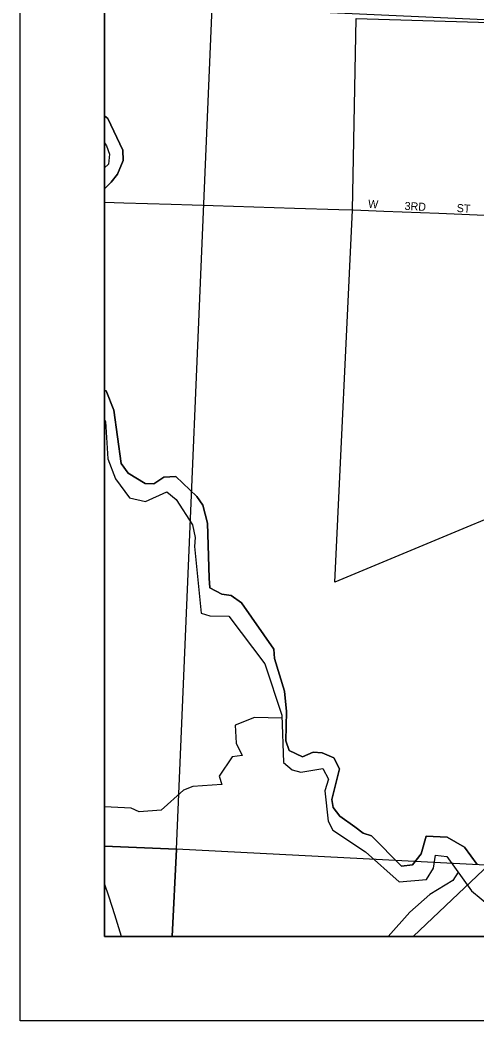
# Model space of a CAD drawing. Extents: x 0 to 34, y 0 to 22.
# Drawn here: x 23.917 to 24.458, y 14 to 15.184 of the extents above; entities that cross this region are included whole.
import ezdxf

# ---------------------------------------------------------------- set-up
doc = ezdxf.new("R2010")
doc.units = 0
for name, color, linetype in [('GM_X_Adjacent_County', 7, 'Continuous'), ('GM_X_City_Street', 7, 'Continuous'), ('GM_X_City_Street_Text', 7, 'Continuous'), ('GM_X_Corporation', 7, 'Continuous'), ('GM_X_County', 7, 'Continuous'), ('GM_X_County_Road', 7, 'Continuous'), ('GM_X_Minor_River', 7, 'Continuous'), ('GM_X_Section', 7, 'Continuous'), ('GM_X_Township', 7, 'Continuous'), ('GM_X_Township_Road', 7, 'Continuous'), ('SH_Data', 7, 'Continuous')]:
    doc.layers.add(name, color=color, linetype=linetype)

msp = doc.modelspace()

# ---------------------------------------------------------------- linework, layer by layer
at = {"layer": 'GM_X_Adjacent_County'}
msp.add_lwpolyline([(24.0167, 18.0693), (24.0167, 14.1), (30.8167, 14.1), (30.8167, 17.8174)], dxfattribs=at)
at = {"layer": 'GM_X_City_Street'}
msp.add_lwpolyline([(24.3111, 14.9597), (24.3112, 14.9597), (24.3473, 14.9583), (24.4126, 14.9558), (24.476, 14.9533)], dxfattribs=at)
at = {"layer": 'GM_X_Corporation'}
msp.add_lwpolyline([(25.6279, 15.253), (25.399, 15.0362), (25.3871, 15.0255), (25.3906, 15.0196), (25.3564, 14.389), (25.0022, 14.3996), (24.6145, 14.4222), (24.623, 14.6582), (24.2893, 14.5192), (24.3104, 14.9594), (24.3146, 15.1862), (24.6178, 15.1772), (24.7267, 15.1736), (24.7351, 15.3783)], dxfattribs=at)
at = {"layer": 'GM_X_County'}
msp.add_lwpolyline([(24.0167, 18.0693), (24.0167, 14.1), (30.8167, 14.1), (30.8167, 17.8174)], dxfattribs=at)
at = {"layer": 'GM_X_County_Road'}
for points in [[(24.0167, 14.969), (24.0397, 14.9683), (24.0956, 14.9665), (24.1453, 14.965), (24.2416, 14.9619), (24.2943, 14.9602), (24.3111, 14.9597)], [(24.3821, 14.1), (24.4359, 14.1508), (24.4651, 14.1786), (24.5086, 14.2203), (24.5687, 14.277), (24.6139, 14.3196), (24.6339, 14.3391), (24.6534, 14.3591), (24.6896, 14.3975), (24.6989, 14.4075)]]:
    msp.add_lwpolyline(points, dxfattribs=at)
at = {"layer": 'GM_X_Minor_River'}
for points in [[(24.0167, 14.9847), (24.0245, 14.9926), (24.032, 15.0021), (24.0388, 15.0181), (24.0384, 15.0306), (24.0208, 15.0681), (24.0167, 15.0709)], [(24.0167, 15.0709), (24.0208, 15.0681), (24.0384, 15.0306), (24.0388, 15.0181), (24.032, 15.0021), (24.0245, 14.9926), (24.0167, 14.9847)], [(24.0167, 15.0393), (24.019, 15.0354), (24.0225, 15.0256), (24.0214, 15.0138), (24.0167, 15.0094)], [(24.458, 14.1852), (24.4431, 14.2057), (24.4226, 14.2174), (24.3976, 14.2188), (24.3916, 14.1976), (24.3814, 14.1846), (24.3682, 14.1831), (24.3328, 14.219), (24.3229, 14.2224), (24.3131, 14.2299), (24.2952, 14.2424), (24.2876, 14.2526), (24.2857, 14.2621), (24.295, 14.2985), (24.2882, 14.3114), (24.2745, 14.3174), (24.2639, 14.3182), (24.251, 14.3124), (24.2355, 14.32), (24.2316, 14.3317), (24.2323, 14.3662), (24.2299, 14.3901), (24.2181, 14.4288), (24.2173, 14.4398), (24.1788, 14.4947), (24.1667, 14.5033), (24.1557, 14.5052), (24.1416, 14.5124), (24.1408, 14.5241), (24.1404, 14.537), (24.1387, 14.589), (24.133, 14.6102), (24.1261, 14.6208), (24.101, 14.6443), (24.087, 14.6434), (24.0753, 14.6358), (24.0647, 14.6362), (24.0449, 14.6482), (24.0366, 14.6596), (24.0276, 14.7229), (24.0185, 14.7457), (24.0167, 14.746)], [(24.0167, 14.746), (24.0185, 14.7457), (24.0276, 14.7229), (24.0366, 14.6596), (24.0449, 14.6482), (24.0647, 14.6362), (24.0753, 14.6358), (24.087, 14.6434), (24.101, 14.6443), (24.1261, 14.6208), (24.133, 14.6102), (24.1387, 14.589), (24.1404, 14.537), (24.1408, 14.5241), (24.1416, 14.5124), (24.1557, 14.5052), (24.1667, 14.5033), (24.1788, 14.4947), (24.2173, 14.4398), (24.2181, 14.4288), (24.2299, 14.3901), (24.2323, 14.3662), (24.2316, 14.3317), (24.2355, 14.32), (24.251, 14.3124), (24.2639, 14.3182), (24.2745, 14.3174), (24.2882, 14.3114), (24.295, 14.2985), (24.2857, 14.2621), (24.2876, 14.2526), (24.2952, 14.2424), (24.3131, 14.2299), (24.3229, 14.2224), (24.3328, 14.219), (24.3682, 14.1831), (24.3814, 14.1846), (24.3916, 14.1976), (24.3976, 14.2188), (24.4226, 14.2174), (24.4431, 14.2057), (24.458, 14.1852)], [(24.0167, 14.7119), (24.0178, 14.7092), (24.0206, 14.6652), (24.0298, 14.6414), (24.0465, 14.619), (24.0651, 14.6149), (24.0905, 14.626), (24.1015, 14.6169), (24.1209, 14.587), (24.124, 14.5723), (24.1233, 14.5616), (24.1311, 14.4824), (24.1413, 14.4794), (24.1641, 14.4791), (24.2067, 14.4227), (24.2266, 14.3617), (24.2287, 14.3059), (24.2389, 14.2972), (24.2492, 14.2946), (24.2753, 14.2989), (24.2818, 14.286), (24.2777, 14.2723), (24.2816, 14.2363), (24.2869, 14.2257), (24.3257, 14.2), (24.3656, 14.1645), (24.3978, 14.1676), (24.4061, 14.1809), (24.4087, 14.1961), (24.4219, 14.1946), (24.4512, 14.1541), (24.474, 14.1352)], [(24.2267, 14.3585), (24.1944, 14.3593), (24.1713, 14.3501), (24.1725, 14.3289), (24.1798, 14.3141), (24.1677, 14.3126), (24.1526, 14.2898), (24.1556, 14.2799), (24.1212, 14.2775), (24.1102, 14.2733), (24.0837, 14.2493), (24.0576, 14.2474), (24.0481, 14.2519), (24.0167, 14.2534)], [(24.4353, 14.1761), (24.4292, 14.1662), (24.402, 14.1498), (24.3782, 14.1289), (24.3525, 14.1)]]:
    msp.add_lwpolyline(points, dxfattribs=at)
at = {"layer": 'GM_X_Section'}
for p, q in [((24.0167, 15.2043), (24.0167, 14.2067)), ((24.097, 14.1), (25.1065, 14.1))]:
    msp.add_line(p, q, dxfattribs=at)
for points in [[(24.0167, 14.2067), (24.102, 14.2034), (24.144, 15.1997), (24.0167, 15.2043)], [(24.0167, 14.2067), (24.0167, 14.1), (24.097, 14.1)], [(24.097, 14.1), (24.102, 14.2034), (24.0167, 14.2067)], [(25.1065, 14.1), (25.1079, 14.1514), (24.102, 14.2034), (24.097, 14.1)]]:
    msp.add_lwpolyline(points, dxfattribs=at)
msp.add_lwpolyline([(24.144, 15.1997), (25.1469, 15.1542), (25.1079, 14.1514), (24.102, 14.2034)], close=True, dxfattribs=at)
at = {"layer": 'GM_X_Township'}
msp.add_lwpolyline([(24.0167, 18.0693), (24.0167, 14.1), (26.1244, 14.1)], dxfattribs=at)
at = {"layer": 'GM_X_Township_Road'}
msp.add_lwpolyline([(24.0367, 14.1), (24.0291, 14.1258), (24.0224, 14.1464), (24.0167, 14.1628)], dxfattribs=at)
at = {"layer": 'SH_Data'}
for points in [[(23.9167, 21), (30.9167, 21), (30.9167, 14), (23.9167, 14)], [(24.0167, 20.9), (30.8167, 20.9), (30.8167, 14.1), (24.0167, 14.1)]]:
    msp.add_lwpolyline(points, close=True, dxfattribs=at)

# ---------------------------------------------------------------- texts
at = {"layer": 'GM_X_City_Street_Text'}
for s, rotation, p in [('W', 355.5872, (24.3285, 14.9624)), ('3RD', 356.8219, (24.3718, 14.9599)), ('ST', 356.4262, (24.4335, 14.9574))]:
    msp.add_text(s, height=0.00947, rotation=rotation, dxfattribs=at).set_placement(p)

doc.saveas('drawing.dxf')
